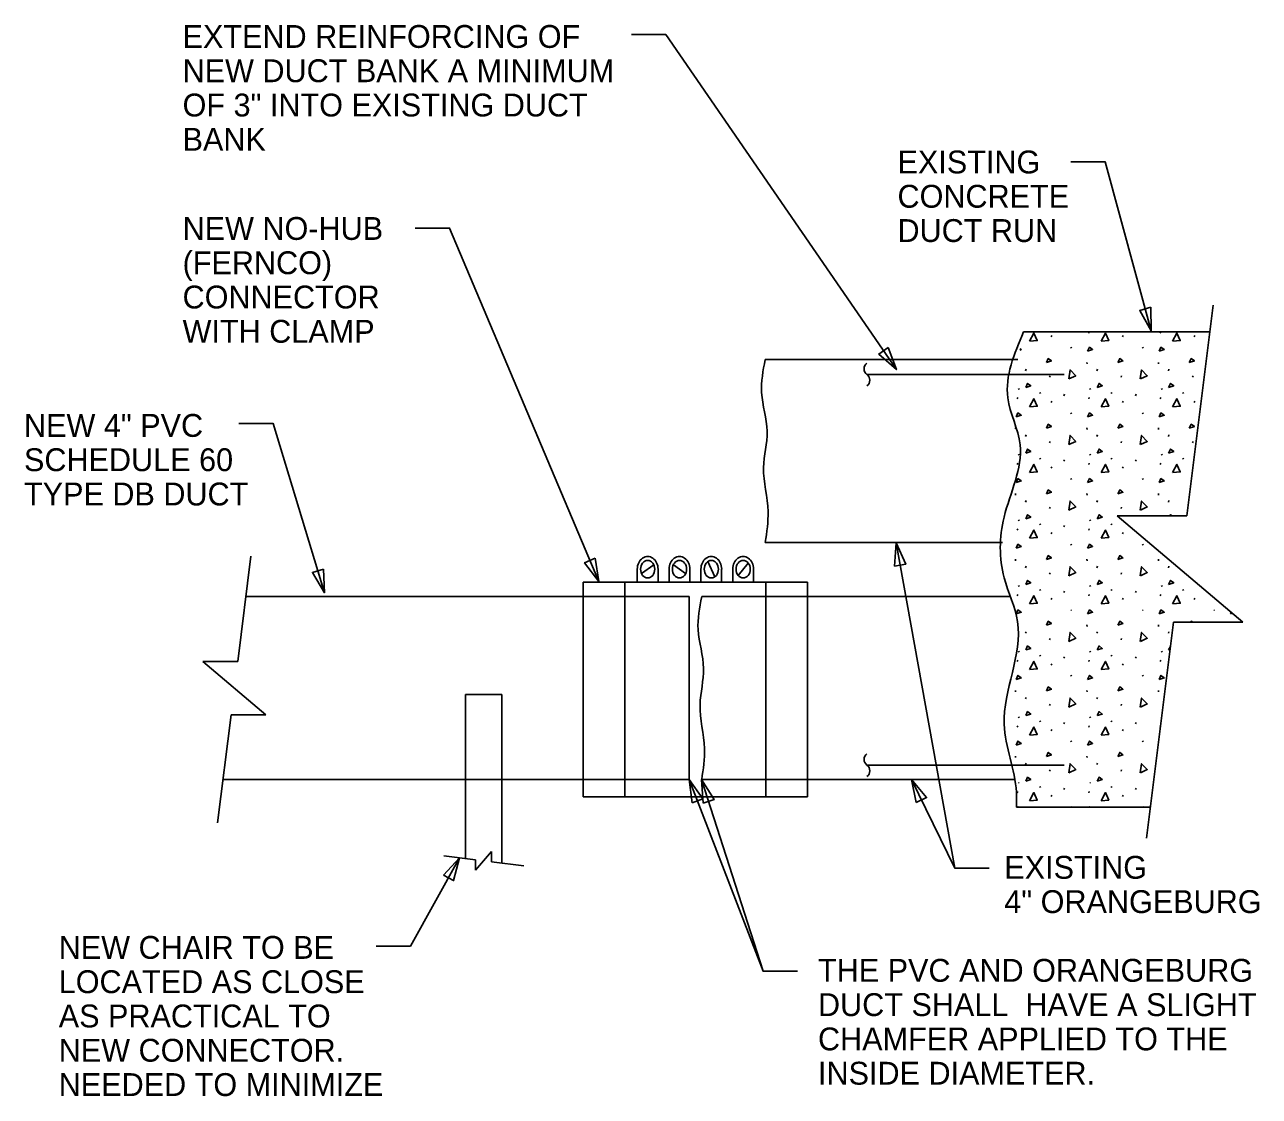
# Model space of a CAD drawing. Extents: x 10012.1 to 10048.7, y 9901.7 to 9957.2.
# Drawn here: x 10012.12 to 10048.11, y 9925.96 to 9957.21 of the extents above; entities that cross this region are included whole.
import ezdxf

# ---------------------------------------------------------------- set-up
doc = ezdxf.new("R2010")
doc.units = 0
for name, color, linetype in [('Default', 7, 'Continuous'), ('G-ANNO-TEXT', 7, 'Continuous'), ('G-TITL-TEXT', 7, 'Continuous')]:
    doc.layers.add(name, color=color, linetype=linetype)

msp = doc.modelspace()

# ---------------------------------------------------------------- linework, layer by layer
at = {"layer": 'Default'}
for p, q in [((10046.758, 9949.038), (10045.989, 9942.887)), ((10041.235, 9948.254), (10046.659, 9948.254)), ((10041.064, 9947.447), (10033.705, 9947.447)), ((10045.99, 9942.888), (10043.965, 9942.888)), ((10047.627, 9939.786), (10043.965, 9942.888)), ((10040.619, 9942.114), (10033.705, 9942.114)), ((10018.717, 9941.714), (10018.332, 9938.638)), ((10029.978, 9941.333), (10029.978, 9940.954)), ((10030.101, 9941.206), (10030.46, 9941.46)), ((10030.582, 9941.333), (10030.582, 9940.954)), ((10030.905, 9941.333), (10030.905, 9940.954)), ((10031.028, 9941.46), (10031.387, 9941.206)), ((10031.509, 9941.333), (10031.509, 9940.954)), ((10031.833, 9940.954), (10031.833, 9941.333)), ((10032.031, 9941.554), (10032.238, 9941.112)), ((10032.436, 9940.954), (10032.436, 9941.333)), ((10032.76, 9940.954), (10032.76, 9941.333)), ((10032.915, 9941.153), (10033.208, 9941.513)), ((10033.364, 9940.954), (10033.364, 9941.333)), ((10034.94, 9940.954), (10028.402, 9940.954)), ((10028.402, 9940.954), (10028.402, 9934.699)), ((10029.618, 9940.954), (10029.618, 9934.699)), ((10033.724, 9940.954), (10033.724, 9934.699)), ((10034.94, 9940.954), (10034.94, 9934.699)), ((10028.402, 9940.534), (10018.586, 9940.534)), ((10031.492, 9940.534), (10028.402, 9940.534)), ((10031.492, 9940.534), (10031.492, 9935.2)), ((10034.94, 9940.534), (10031.854, 9940.534)), ((10040.842, 9940.534), (10034.94, 9940.534)), ((10045.602, 9939.786), (10044.816, 9933.493)), ((10047.627, 9939.786), (10045.602, 9939.786)), ((10018.333, 9938.638), (10017.32, 9938.638)), ((10019.151, 9937.087), (10017.32, 9938.638)), ((10018.139, 9937.087), (10017.746, 9933.941)), ((10019.151, 9937.087), (10018.139, 9937.087)), ((10024.968, 9935.2), (10017.895, 9935.2)), ((10026.032, 9935.2), (10024.968, 9935.2)), ((10028.402, 9935.2), (10026.032, 9935.2)), ((10031.492, 9935.2), (10028.402, 9935.2)), ((10034.94, 9935.2), (10031.853, 9935.2)), ((10040.99, 9935.2), (10034.94, 9935.2)), ((10034.94, 9934.699), (10028.402, 9934.699)), ((10044.928, 9934.394), (10041.027, 9934.394)), ((10024.338, 9932.972), (10025.26, 9932.857)), ((10025.726, 9933.103), (10025.26, 9932.553)), ((10025.726, 9933.103), (10025.726, 9932.799)), ((10025.26, 9932.857), (10025.26, 9932.553)), ((10025.726, 9932.799), (10026.67, 9932.681))]:
    msp.add_line(p, q, dxfattribs=at)
for centre in [(10030.28, 9941.333), (10031.207, 9941.333), (10032.135, 9941.333), (10033.062, 9941.333)]:
    msp.add_ellipse(centre, major_axis=(0, 0.372), ratio=0.812083, start_param=4.712389, end_param=7.853982, dxfattribs=at)
for points in [[(10041.235, 9948.254), (10040.775, 9946.331), (10041.133, 9944.965), (10040.668, 9942.849), (10040.668, 9941.086), (10041.062, 9939.808), (10040.668, 9936.811), (10041.026, 9934.828), (10041.026, 9934.394)], [(10033.705, 9947.447), (10033.6, 9946.484), (10033.761, 9945.355), (10033.657, 9944.296), (10033.789, 9943.015), (10033.705, 9942.114)], [(10031.854, 9940.534), (10031.749, 9939.571), (10031.91, 9938.442), (10031.806, 9937.383), (10031.938, 9936.102), (10031.854, 9935.2)]]:
    msp.add_spline(points, degree=3, dxfattribs=at)
at = {"layer": 'G-ANNO-TEXT'}
for p, q in [((10042.038, 9948.106), (10042.056, 9948.147)), ((10043.134, 9948.212), (10043.152, 9948.254)), ((10044.121, 9948.106), (10044.139, 9948.147)), ((10045.217, 9948.212), (10045.236, 9948.254)), ((10046.204, 9948.106), (10046.223, 9948.147)), ((10042.616, 9947.81), (10042.634, 9947.782)), ((10044.699, 9947.81), (10044.718, 9947.782)), ((10043.083, 9947.366), (10043.088, 9947.324)), ((10045.167, 9947.366), (10045.171, 9947.324)), ((10042.422, 9947.011), (10036.671, 9947.011)), ((10041.288, 9947.12), (10041.307, 9947.162)), ((10041.991, 9946.931), (10042.01, 9946.973)), ((10043.372, 9947.12), (10043.39, 9947.162)), ((10044.075, 9946.931), (10044.093, 9946.973)), ((10045.455, 9947.12), (10045.473, 9947.162)), ((10046.158, 9946.931), (10046.177, 9946.973)), ((10041.05, 9946.298), (10041.069, 9946.339)), ((10041.085, 9946.603), (10041.104, 9946.575)), ((10041.708, 9946.485), (10041.727, 9946.457)), ((10042.412, 9946.394), (10042.431, 9946.436)), ((10043.134, 9946.298), (10043.152, 9946.339)), ((10043.169, 9946.603), (10043.187, 9946.575)), ((10043.792, 9946.485), (10043.81, 9946.457)), ((10044.496, 9946.394), (10044.514, 9946.436)), ((10045.217, 9946.298), (10045.236, 9946.339)), ((10045.252, 9946.603), (10045.271, 9946.575)), ((10045.875, 9946.485), (10045.894, 9946.457)), ((10042.038, 9946.191), (10042.056, 9946.233)), ((10042.616, 9945.895), (10042.634, 9945.868)), ((10044.121, 9946.191), (10044.139, 9946.233)), ((10044.699, 9945.895), (10044.718, 9945.868)), ((10046.204, 9946.191), (10046.223, 9946.233)), ((10041, 9945.452), (10041.002, 9945.431)), ((10041.288, 9945.206), (10041.307, 9945.248)), ((10043.083, 9945.452), (10043.088, 9945.41)), ((10043.372, 9945.206), (10043.39, 9945.248)), ((10045.167, 9945.452), (10045.171, 9945.41)), ((10045.455, 9945.206), (10045.473, 9945.248)), ((10041.991, 9945.017), (10042.01, 9945.058)), ((10044.075, 9945.017), (10044.093, 9945.058)), ((10046.158, 9945.017), (10046.177, 9945.058)), ((10041.085, 9944.688), (10041.104, 9944.661)), ((10041.708, 9944.571), (10041.727, 9944.543)), ((10042.412, 9944.48), (10042.431, 9944.522)), ((10043.169, 9944.688), (10043.187, 9944.661)), ((10043.792, 9944.571), (10043.81, 9944.543)), ((10044.496, 9944.48), (10044.514, 9944.522)), ((10045.252, 9944.688), (10045.271, 9944.661)), ((10045.875, 9944.571), (10045.894, 9944.543)), ((10041.05, 9944.384), (10041.069, 9944.425)), ((10042.038, 9944.277), (10042.056, 9944.319)), ((10043.134, 9944.384), (10043.152, 9944.425)), ((10044.121, 9944.277), (10044.139, 9944.319)), ((10045.217, 9944.384), (10045.236, 9944.425)), ((10042.616, 9943.981), (10042.634, 9943.953)), ((10044.699, 9943.981), (10044.718, 9943.953)), ((10041, 9943.538), (10041.005, 9943.496)), ((10043.083, 9943.538), (10043.088, 9943.496)), ((10045.167, 9943.538), (10045.171, 9943.496)), ((10041.288, 9943.292), (10041.307, 9943.334)), ((10041.991, 9943.102), (10042.01, 9943.144)), ((10043.372, 9943.292), (10043.39, 9943.334)), ((10044.075, 9943.102), (10044.093, 9943.144)), ((10045.455, 9943.292), (10045.473, 9943.334)), ((10041.085, 9942.774), (10041.104, 9942.746)), ((10041.708, 9942.656), (10041.727, 9942.629)), ((10043.169, 9942.774), (10043.187, 9942.746)), ((10043.792, 9942.656), (10043.81, 9942.629)), ((10041.05, 9942.469), (10041.069, 9942.511)), ((10042.038, 9942.363), (10042.056, 9942.405)), ((10042.412, 9942.566), (10042.431, 9942.608)), ((10043.134, 9942.469), (10043.152, 9942.511)), ((10044.121, 9942.363), (10044.139, 9942.405)), ((10039.231, 9932.616), (10037.52, 9942.104)), ((10042.616, 9942.067), (10042.634, 9942.039)), ((10044.699, 9942.067), (10044.718, 9942.039)), ((10041, 9941.623), (10041.005, 9941.582)), ((10043.083, 9941.623), (10043.088, 9941.582)), ((10045.167, 9941.623), (10045.171, 9941.582)), ((10041.288, 9941.378), (10041.307, 9941.419)), ((10041.991, 9941.188), (10042.01, 9941.23)), ((10043.372, 9941.378), (10043.39, 9941.419)), ((10044.075, 9941.188), (10044.093, 9941.23)), ((10045.455, 9941.378), (10045.473, 9941.419)), ((10041.085, 9940.86), (10041.104, 9940.832)), ((10043.169, 9940.86), (10043.187, 9940.832)), ((10045.252, 9940.86), (10045.271, 9940.832)), ((10041.05, 9940.555), (10041.069, 9940.597)), ((10041.708, 9940.742), (10041.727, 9940.714)), ((10042.412, 9940.652), (10042.431, 9940.693)), ((10043.134, 9940.555), (10043.152, 9940.597)), ((10043.792, 9940.742), (10043.81, 9940.714)), ((10044.496, 9940.652), (10044.514, 9940.693)), ((10045.217, 9940.555), (10045.236, 9940.597)), ((10045.875, 9940.742), (10045.894, 9940.714)), ((10046.579, 9940.652), (10046.586, 9940.668)), ((10042.038, 9940.449), (10042.056, 9940.49)), ((10042.616, 9940.153), (10042.634, 9940.125)), ((10044.121, 9940.449), (10044.139, 9940.49)), ((10044.699, 9940.153), (10044.718, 9940.125)), ((10046.204, 9940.449), (10046.223, 9940.49)), ((10046.782, 9940.153), (10046.801, 9940.125)), ((10041.288, 9939.464), (10041.307, 9939.505)), ((10043.083, 9939.709), (10043.088, 9939.667)), ((10043.372, 9939.464), (10043.39, 9939.505)), ((10045.167, 9939.709), (10045.171, 9939.667)), ((10045.455, 9939.464), (10045.473, 9939.505)), ((10041.991, 9939.274), (10042.01, 9939.316)), ((10044.075, 9939.274), (10044.093, 9939.316)), ((10041.085, 9938.946), (10041.104, 9938.918)), ((10041.708, 9938.828), (10041.727, 9938.8)), ((10042.412, 9938.738), (10042.431, 9938.779)), ((10043.169, 9938.946), (10043.187, 9938.918)), ((10043.792, 9938.828), (10043.81, 9938.8)), ((10044.496, 9938.738), (10044.514, 9938.779)), ((10045.252, 9938.946), (10045.271, 9938.918)), ((10041.05, 9938.641), (10041.069, 9938.683)), ((10042.038, 9938.535), (10042.056, 9938.576)), ((10043.134, 9938.641), (10043.152, 9938.683)), ((10044.121, 9938.535), (10044.139, 9938.576)), ((10045.217, 9938.641), (10045.236, 9938.683)), ((10042.616, 9938.239), (10042.634, 9938.211)), ((10044.699, 9938.239), (10044.718, 9938.211)), ((10024.968, 9937.678), (10024.968, 9932.895)), ((10024.968, 9937.678), (10026.032, 9937.678)), ((10026.032, 9937.678), (10026.032, 9932.761)), ((10041, 9937.795), (10041.005, 9937.753)), ((10043.083, 9937.795), (10043.088, 9937.753)), ((10045.167, 9937.795), (10045.171, 9937.753)), ((10041.288, 9937.549), (10041.307, 9937.591)), ((10041.991, 9937.36), (10042.01, 9937.401)), ((10043.372, 9937.549), (10043.39, 9937.591)), ((10044.075, 9937.36), (10044.093, 9937.401)), ((10041.085, 9937.032), (10041.104, 9937.004)), ((10041.708, 9936.914), (10041.727, 9936.886)), ((10043.169, 9937.032), (10043.187, 9937.004)), ((10043.792, 9936.914), (10043.81, 9936.886)), ((10045.252, 9937.032), (10045.257, 9937.025)), ((10041.05, 9936.727), (10041.069, 9936.768)), ((10042.038, 9936.62), (10042.056, 9936.662)), ((10042.412, 9936.823), (10042.431, 9936.865)), ((10043.134, 9936.727), (10043.152, 9936.768)), ((10044.121, 9936.62), (10044.139, 9936.662)), ((10044.496, 9936.823), (10044.514, 9936.865)), ((10045.217, 9936.727), (10045.22, 9936.734)), ((10042.616, 9936.324), (10042.634, 9936.297)), ((10044.699, 9936.324), (10044.718, 9936.297)), ((10041, 9935.881), (10041.005, 9935.839)), ((10043.083, 9935.881), (10043.088, 9935.839)), ((10042.422, 9935.62), (10036.671, 9935.62)), ((10041.288, 9935.635), (10041.307, 9935.677)), ((10041.991, 9935.446), (10042.01, 9935.487)), ((10043.372, 9935.635), (10043.39, 9935.677)), ((10044.075, 9935.446), (10044.093, 9935.487)), ((10033.646, 9929.607), (10031.492, 9935.2)), ((10041.085, 9935.117), (10041.104, 9935.09)), ((10043.169, 9935.117), (10043.187, 9935.09)), ((10041.05, 9934.812), (10041.069, 9934.854)), ((10041.708, 9935), (10041.727, 9934.972)), ((10042.038, 9934.706), (10042.056, 9934.748)), ((10042.412, 9934.909), (10042.431, 9934.951)), ((10043.134, 9934.812), (10043.152, 9934.854)), ((10043.792, 9935), (10043.81, 9934.972)), ((10044.121, 9934.706), (10044.139, 9934.748)), ((10044.496, 9934.909), (10044.514, 9934.951)), ((10042.616, 9934.41), (10042.627, 9934.394)), ((10044.699, 9934.41), (10044.71, 9934.394))]:
    msp.add_line(p, q, dxfattribs=at)
for points in [[(10029.805, 9956.928), (10030.805, 9956.928), (10037.529, 9947.154)], [(10042.609, 9953.214), (10043.609, 9953.214), (10044.956, 9948.283)], [(10023.507, 9951.283), (10024.507, 9951.283), (10028.854, 9940.975)], [(10041.413, 9947.981), (10041.538, 9948.217), (10041.635, 9947.999), (10041.418, 9947.981)], [(10043.497, 9947.981), (10043.621, 9948.217), (10043.719, 9947.999), (10043.501, 9947.981)], [(10045.58, 9947.981), (10045.705, 9948.217), (10045.802, 9947.999), (10045.584, 9947.981)], [(10041.131, 9947.762), (10041.166, 9947.736), (10041.123, 9947.722)], [(10043.101, 9947.689), (10043.157, 9947.805), (10043.249, 9947.736), (10043.101, 9947.689)], [(10045.185, 9947.689), (10045.24, 9947.805), (10045.333, 9947.736), (10045.185, 9947.689)], [(10041.9, 9947.359), (10041.955, 9947.474), (10042.048, 9947.405), (10041.9, 9947.359)], [(10043.983, 9947.359), (10044.039, 9947.474), (10044.131, 9947.405), (10043.983, 9947.359)], [(10046.066, 9947.359), (10046.122, 9947.474), (10046.214, 9947.405), (10046.066, 9947.359)], [(10042.554, 9946.883), (10042.591, 9947.147), (10042.756, 9946.976), (10042.558, 9946.885)], [(10044.637, 9946.883), (10044.674, 9947.147), (10044.84, 9946.976), (10044.642, 9946.885)], [(10041.298, 9946.635), (10041.353, 9946.75), (10041.446, 9946.681), (10041.298, 9946.635)], [(10043.381, 9946.635), (10043.436, 9946.75), (10043.529, 9946.681), (10043.381, 9946.635)], [(10045.464, 9946.635), (10045.52, 9946.75), (10045.612, 9946.681), (10045.464, 9946.635)], [(10041.413, 9946.067), (10041.538, 9946.302), (10041.635, 9946.085), (10041.418, 9946.067)], [(10043.497, 9946.067), (10043.621, 9946.302), (10043.719, 9946.085), (10043.501, 9946.067)], [(10045.58, 9946.067), (10045.705, 9946.302), (10045.802, 9946.085), (10045.584, 9946.067)], [(10041.018, 9945.775), (10041.073, 9945.891), (10041.166, 9945.821), (10041.018, 9945.775)], [(10043.101, 9945.775), (10043.157, 9945.891), (10043.249, 9945.821), (10043.101, 9945.775)], [(10045.185, 9945.775), (10045.24, 9945.891), (10045.333, 9945.821), (10045.185, 9945.775)], [(10018.367, 9945.579), (10019.367, 9945.579), (10020.863, 9940.648)], [(10041.9, 9945.445), (10041.955, 9945.56), (10042.048, 9945.491), (10041.9, 9945.445)], [(10043.983, 9945.445), (10044.039, 9945.56), (10044.131, 9945.491), (10043.983, 9945.445)], [(10046.066, 9945.445), (10046.122, 9945.56), (10046.214, 9945.491), (10046.066, 9945.445)], [(10042.554, 9944.969), (10042.591, 9945.233), (10042.756, 9945.062), (10042.558, 9944.97)], [(10044.637, 9944.969), (10044.674, 9945.233), (10044.84, 9945.062), (10044.642, 9944.97)], [(10041.298, 9944.721), (10041.353, 9944.836), (10041.446, 9944.767), (10041.298, 9944.721)], [(10043.381, 9944.721), (10043.436, 9944.836), (10043.529, 9944.767), (10043.381, 9944.721)], [(10045.464, 9944.721), (10045.52, 9944.836), (10045.612, 9944.767), (10045.464, 9944.721)], [(10041.413, 9944.152), (10041.538, 9944.388), (10041.635, 9944.171), (10041.418, 9944.152)], [(10043.497, 9944.152), (10043.621, 9944.388), (10043.719, 9944.171), (10043.501, 9944.152)], [(10045.58, 9944.152), (10045.705, 9944.388), (10045.802, 9944.171), (10045.584, 9944.152)], [(10041.018, 9943.861), (10041.073, 9943.977), (10041.166, 9943.907), (10041.018, 9943.861)], [(10043.101, 9943.861), (10043.157, 9943.977), (10043.249, 9943.907), (10043.101, 9943.861)], [(10045.185, 9943.861), (10045.24, 9943.977), (10045.333, 9943.907), (10045.185, 9943.861)], [(10041.9, 9943.53), (10041.955, 9943.646), (10042.048, 9943.577), (10041.9, 9943.53)], [(10043.983, 9943.53), (10044.039, 9943.646), (10044.131, 9943.577), (10043.983, 9943.53)], [(10046.066, 9943.53), (10046.072, 9943.542)], [(10046.071, 9943.532), (10046.066, 9943.53)], [(10042.554, 9943.055), (10042.591, 9943.319), (10042.756, 9943.148), (10042.558, 9943.056)], [(10044.637, 9943.055), (10044.674, 9943.319), (10044.84, 9943.148), (10044.642, 9943.056)], [(10041.298, 9942.806), (10041.353, 9942.922), (10041.446, 9942.853), (10041.298, 9942.806)], [(10043.381, 9942.806), (10043.436, 9942.922), (10043.529, 9942.853), (10043.381, 9942.806)], [(10045.503, 9942.887), (10045.52, 9942.922), (10045.566, 9942.887)], [(10041.413, 9942.238), (10041.538, 9942.474), (10041.635, 9942.257), (10041.418, 9942.238)], [(10043.497, 9942.238), (10043.621, 9942.474), (10043.719, 9942.257), (10043.501, 9942.238)], [(10041.018, 9941.947), (10041.073, 9942.062), (10041.166, 9941.993), (10041.018, 9941.947)], [(10043.101, 9941.947), (10043.157, 9942.062), (10043.249, 9941.993), (10043.101, 9941.947)], [(10041.9, 9941.616), (10041.955, 9941.732), (10042.048, 9941.662), (10041.9, 9941.616)], [(10043.983, 9941.616), (10044.039, 9941.732), (10044.131, 9941.662), (10043.983, 9941.616)], [(10042.554, 9941.14), (10042.591, 9941.405), (10042.756, 9941.234), (10042.558, 9941.142)], [(10044.637, 9941.14), (10044.674, 9941.405), (10044.84, 9941.234), (10044.642, 9941.142)], [(10041.298, 9940.892), (10041.353, 9941.008), (10041.446, 9940.938), (10041.298, 9940.892)], [(10043.381, 9940.892), (10043.436, 9941.008), (10043.529, 9940.938), (10043.381, 9940.892)], [(10045.464, 9940.892), (10045.52, 9941.008), (10045.612, 9940.938), (10045.464, 9940.892)], [(10041.413, 9940.324), (10041.538, 9940.56), (10041.635, 9940.342), (10041.418, 9940.324)], [(10043.497, 9940.324), (10043.621, 9940.56), (10043.719, 9940.342), (10043.501, 9940.324)], [(10045.58, 9940.324), (10045.705, 9940.56), (10045.802, 9940.342), (10045.584, 9940.324)], [(10041.018, 9940.033), (10041.073, 9940.148), (10041.166, 9940.079), (10041.018, 9940.033)], [(10043.101, 9940.033), (10043.157, 9940.148), (10043.249, 9940.079), (10043.101, 9940.033)], [(10045.185, 9940.033), (10045.24, 9940.148), (10045.333, 9940.079), (10045.185, 9940.033)], [(10041.9, 9939.702), (10041.955, 9939.818), (10042.048, 9939.748), (10041.9, 9939.702)], [(10043.983, 9939.702), (10044.039, 9939.818), (10044.131, 9939.748), (10043.983, 9939.702)], [(10046.107, 9939.786), (10046.122, 9939.818), (10046.164, 9939.786)], [(10047.268, 9940.033), (10047.288, 9940.073)], [(10047.318, 9940.048), (10047.268, 9940.033)], [(10042.554, 9939.226), (10042.591, 9939.49), (10042.756, 9939.319), (10042.558, 9939.228)], [(10044.637, 9939.226), (10044.674, 9939.49), (10044.84, 9939.319), (10044.642, 9939.228)], [(10041.298, 9938.978), (10041.353, 9939.094), (10041.446, 9939.024), (10041.298, 9938.978)], [(10043.381, 9938.978), (10043.436, 9939.094), (10043.529, 9939.024), (10043.381, 9938.978)], [(10045.464, 9938.978), (10045.514, 9939.081)], [(10045.502, 9938.99), (10045.464, 9938.978)], [(10041.413, 9938.41), (10041.538, 9938.646), (10041.635, 9938.428), (10041.418, 9938.41)], [(10043.497, 9938.41), (10043.621, 9938.646), (10043.719, 9938.428), (10043.501, 9938.41)], [(10041.018, 9938.118), (10041.073, 9938.234), (10041.166, 9938.165), (10041.018, 9938.118)], [(10043.101, 9938.118), (10043.157, 9938.234), (10043.249, 9938.165), (10043.101, 9938.118)], [(10045.185, 9938.118), (10045.24, 9938.234), (10045.333, 9938.165), (10045.185, 9938.118)], [(10041.9, 9937.788), (10041.955, 9937.903), (10042.048, 9937.834), (10041.9, 9937.788)], [(10043.983, 9937.788), (10044.039, 9937.903), (10044.131, 9937.834), (10043.983, 9937.788)], [(10042.554, 9937.312), (10042.591, 9937.576), (10042.756, 9937.405), (10042.558, 9937.314)], [(10044.637, 9937.312), (10044.674, 9937.576), (10044.84, 9937.405), (10044.642, 9937.314)], [(10041.298, 9937.064), (10041.353, 9937.179), (10041.446, 9937.11), (10041.298, 9937.064)], [(10043.381, 9937.064), (10043.436, 9937.179), (10043.529, 9937.11), (10043.381, 9937.064)], [(10041.413, 9936.495), (10041.538, 9936.731), (10041.635, 9936.514), (10041.418, 9936.495)], [(10043.497, 9936.495), (10043.621, 9936.731), (10043.719, 9936.514), (10043.501, 9936.495)], [(10041.018, 9936.204), (10041.073, 9936.32), (10041.166, 9936.25), (10041.018, 9936.204)], [(10043.101, 9936.204), (10043.157, 9936.32), (10043.249, 9936.25), (10043.101, 9936.204)], [(10041.9, 9935.873), (10041.955, 9935.989), (10042.048, 9935.92), (10041.9, 9935.873)], [(10043.983, 9935.873), (10044.039, 9935.989), (10044.131, 9935.92), (10043.983, 9935.873)], [(10042.554, 9935.398), (10042.591, 9935.662), (10042.756, 9935.491), (10042.558, 9935.399)], [(10044.637, 9935.398), (10044.674, 9935.662), (10044.84, 9935.491), (10044.642, 9935.399)], [(10034.646, 9929.607), (10033.646, 9929.607), (10031.853, 9935.2)], [(10040.231, 9932.616), (10039.231, 9932.616), (10037.965, 9935.2)], [(10041.298, 9935.15), (10041.353, 9935.265), (10041.446, 9935.196), (10041.298, 9935.15)], [(10043.381, 9935.15), (10043.436, 9935.265), (10043.529, 9935.196), (10043.381, 9935.15)], [(10041.413, 9934.581), (10041.538, 9934.817), (10041.635, 9934.6), (10041.418, 9934.581)], [(10043.497, 9934.581), (10043.621, 9934.817), (10043.719, 9934.6), (10043.501, 9934.581)], [(10041.068, 9934.394), (10041.073, 9934.405), (10041.089, 9934.394)], [(10043.151, 9934.394), (10043.157, 9934.405), (10043.173, 9934.394)], [(10022.365, 9930.338), (10023.365, 9930.338), (10024.799, 9932.915)]]:
    msp.add_lwpolyline(points, dxfattribs=at)
for points in [[(10044.941, 9948.97), (10044.956, 9948.283), (10044.619, 9948.882)], [(10037.288, 9947.798), (10037.529, 9947.154), (10037.014, 9947.609)], [(10037.474, 9941.418), (10037.52, 9942.104), (10037.802, 9941.477)], [(10028.749, 9941.654), (10028.854, 9940.975), (10028.442, 9941.524)], [(10020.829, 9941.334), (10020.863, 9940.648), (10020.51, 9941.238)], [(10031.576, 9934.518), (10031.492, 9935.2), (10031.887, 9934.638)], [(10031.898, 9934.515), (10031.853, 9935.2), (10032.215, 9934.617)], [(10038.108, 9934.528), (10037.965, 9935.2), (10038.408, 9934.675)], [(10024.329, 9932.413), (10024.799, 9932.915), (10024.621, 9932.251)]]:
    msp.add_lwpolyline(points, close=True, dxfattribs=at)
for centre, start, end in [((10036.796, 9947.177), 126.8699, 233.1301), ((10036.546, 9946.844), 306.8699, 53.1301), ((10036.796, 9935.786), 126.8699, 233.1301), ((10036.546, 9935.453), 306.8699, 53.1301)]:
    msp.add_arc(centre, 0.208, start, end, dxfattribs=at)
at = {"layer": 'G-TITL-TEXT'}
for centre in [(10030.28, 9941.333), (10031.207, 9941.333), (10032.135, 9941.333), (10033.062, 9941.333)]:
    msp.add_ellipse(centre, major_axis=(0, 0.255), ratio=0.812083, dxfattribs=at)

# ---------------------------------------------------------------- texts
at = {"layer": 'G-ANNO-TEXT'}
for s, height, p in [('EXTEND REINFORCING OF', 0.66667, (10016.725, 9956.536)), ('NEW DUCT BANK A MINIMUM', 0.66667, (10016.725, 9955.536)), ('OF 3" INTO EXISTING DUCT', 0.66667, (10016.725, 9954.536)), ('BANK ', 0.6667, (10016.725, 9953.536)), ('EXISTING ', 0.6667, (10037.561, 9952.875)), ('CONCRETE', 0.6667, (10037.561, 9951.875)), ('NEW NO-HUB', 0.6667, (10016.725, 9950.937)), ('DUCT RUN', 0.6667, (10037.561, 9950.875)), ('(FERNCO)', 0.6667, (10016.725, 9949.937)), ('CONNECTOR', 0.6667, (10016.725, 9948.937)), ('WITH CLAMP', 0.6667, (10016.725, 9947.937)), ('NEW 4" PVC', 0.6667, (10012.103, 9945.193)), ('SCHEDULE 60', 0.66667, (10012.103, 9944.193)), ('TYPE DB DUCT', 0.66667, (10012.103, 9943.193)), ('EXISTING ', 0.6667, (10040.673, 9932.306)), ('4" ORANGEBURG', 0.66667, (10040.673, 9931.306)), ('NEW CHAIR TO BE', 0.66667, (10013.115, 9929.971)), ('THE PVC AND ORANGEBURG', 0.66667, (10035.244, 9929.302)), ('LOCATED AS CLOSE', 0.66667, (10013.115, 9928.971)), ('DUCT SHALL  HAVE A SLIGHT', 0.66667, (10035.244, 9928.302)), ('AS PRACTICAL TO ', 0.66667, (10013.115, 9927.971)), ('CHAMFER APPLIED TO THE', 0.66667, (10035.244, 9927.302)), ('NEW CONNECTOR.', 0.66667, (10013.115, 9926.971)), ('INSIDE DIAMETER.', 0.66667, (10035.244, 9926.302)), ('NEEDED TO MINIMIZE', 0.66667, (10013.115, 9925.971))]:
    msp.add_text(s, height=height, dxfattribs=at).set_placement(p)

doc.saveas('drawing.dxf')
